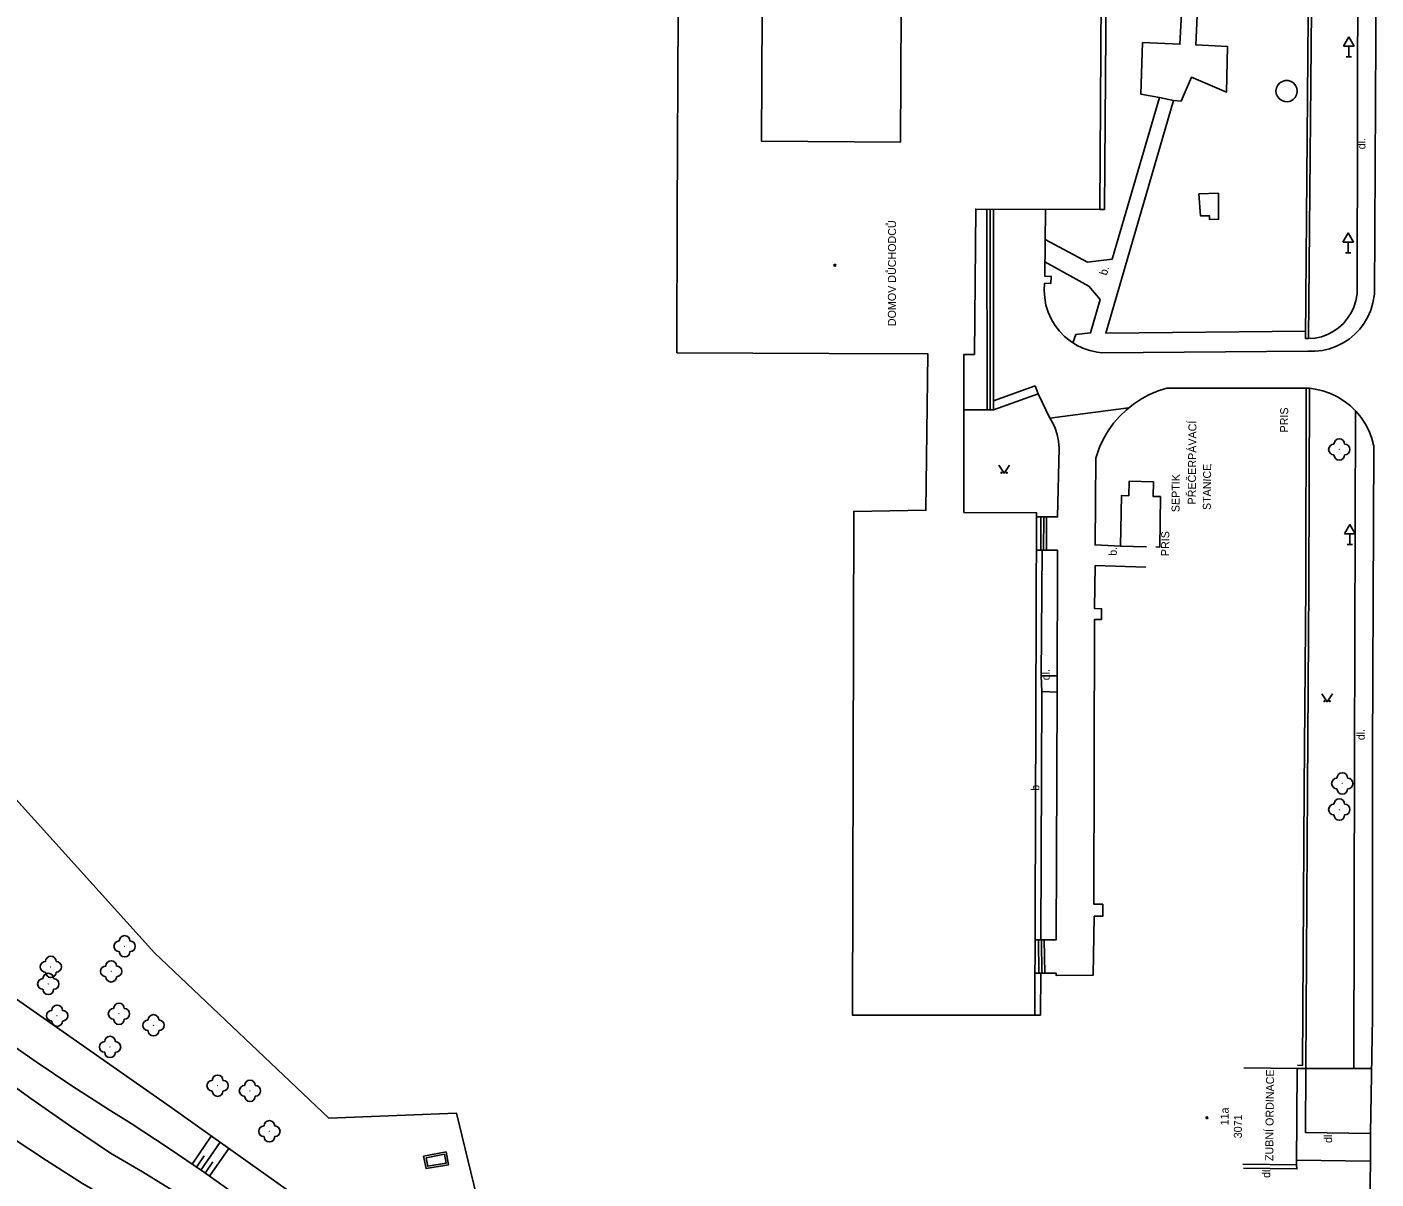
# Model space of a CAD drawing. Extents: x -584400 to -581602, y -1210894 to -1208793.
# Drawn here: x -582970.7 to -582844.2, y -1210177.5 to -1210069.5 of the extents above; entities that cross this region are included whole.
import ezdxf

# ---------------------------------------------------------------- set-up
doc = ezdxf.new("R2010")
doc.units = 0
for name, color, linetype in [('BUDOVY_MĚŘ', 7, 'Continuous'), ('BUDOVY_NEMĚŘ', 7, 'Continuous'), ('POMOC_POPIS', 7, 'Continuous'), ('ROZHRANÍ_PLOCH', 7, 'Continuous'), ('VÝŠKOPIS', 7, 'Continuous'), ('ZELEŇ', 7, 'Continuous'), ('ZN_BUDOV', 7, 'Continuous'), ('ZN_DOPLŇKOVÉ', 7, 'Continuous'), ('ZN_KULTUR', 7, 'Continuous'), ('Č_POPIS_EVID', 7, 'Continuous')]:
    doc.layers.add(name, color=color, linetype=linetype)

msp = doc.modelspace()

# ---------------------------------------------------------------- linework, layer by layer
at = {"layer": 'BUDOVY_MĚŘ'}
for points in [[(-582881.84, -1210100.23), (-582881.73, -1210086.6), (-582870.1, -1210086.64), (-582869.92, -1210061.85), (-582870.29, -1210061.85)], [(-582881.84, -1210100.23), (-582882.83, -1210100.23), (-582882.85, -1210115.05)], [(-582876.17, -1210162.16), (-582876.02, -1210115.06), (-582882.85, -1210115.05)], [(-582851.67, -1210176.18), (-582851.58, -1210167.14), (-582856.58, -1210167.09)], [(-582851.67, -1210176.18), (-582856.67, -1210176.12)]]:
    msp.add_lwpolyline(points, dxfattribs=at)
at = {"layer": 'BUDOVY_NEMĚŘ'}
msp.add_lwpolyline([(-582870.29, -1210061.85), (-582888.67, -1210061.71), (-582888.78, -1210080.34), (-582901.81, -1210080.23), (-582901.75, -1210068.26), (-582909.61, -1210068.22), (-582909.7, -1210087.02), (-582909.73, -1210100.07), (-582895.48, -1210100.14), (-582886.2, -1210100.18), (-582886.4, -1210114.82), (-582893.16, -1210114.94), (-582893.29, -1210162.14), (-582876.17, -1210162.16)], dxfattribs=at)
at = {"layer": 'ROZHRANÍ_PLOCH'}
for points in [[(-582864.49, -1210076.14), (-582866.25, -1210075.83), (-582866.08, -1210070.99), (-582862.58, -1210071.15), (-582862.05, -1210061.26)], [(-582860.63, -1210060.94), (-582861.09, -1210071.22), (-582858.13, -1210071.35), (-582858.21, -1210075.63), (-582861.51, -1210074.25), (-582862.47, -1210076.5), (-582863.17, -1210076.41)], [(-582869.92, -1210061.85), (-582869.47, -1210061.85), (-582869.65, -1210086.64), (-582870.1, -1210086.64)], [(-582845.91, -1210062.34), (-582845.98, -1210094.55)], [(-582875.28, -1210093.55), (-582875.31, -1210094.24), (-582875.26, -1210094.93), (-582875.14, -1210095.6), (-582874.93, -1210096.26), (-582874.65, -1210096.89), (-582874.3, -1210097.48), (-582873.88, -1210098.03), (-582873.4, -1210098.53), (-582872.87, -1210098.96), (-582872.29, -1210099.34), (-582871.67, -1210099.64), (-582871.02, -1210099.87), (-582870.35, -1210100.02), (-582869.89, -1210100.08), (-582850.6, -1210099.93), (-582849.91, -1210099.93), (-582849.23, -1210099.85), (-582848.56, -1210099.69), (-582847.91, -1210099.46), (-582847.29, -1210099.15), (-582846.72, -1210098.78), (-582846.19, -1210098.33), (-582845.72, -1210097.84), (-582845.31, -1210097.28), (-582844.96, -1210096.69), (-582844.69, -1210096.06), (-582844.49, -1210095.4), (-582844.35, -1210094.57), (-582844.2, -1210064.54)], [(-582851.58, -1210075.55), (-582851.62, -1210075.27), (-582851.74, -1210075.01), (-582851.92, -1210074.8), (-582852.16, -1210074.64), (-582852.43, -1210074.56), (-582852.71, -1210074.56), (-582852.98, -1210074.63), (-582853.22, -1210074.78), (-582853.41, -1210074.99), (-582853.53, -1210075.24), (-582853.58, -1210075.52), (-582853.55, -1210075.8), (-582853.44, -1210076.06), (-582853.26, -1210076.28), (-582853.03, -1210076.44), (-582852.76, -1210076.53), (-582852.48, -1210076.54), (-582852.21, -1210076.48), (-582851.96, -1210076.33), (-582851.77, -1210076.13), (-582851.64, -1210075.88), (-582851.58, -1210075.6), (-582851.58, -1210075.55)], [(-582875.21, -1210089.45), (-582871.26, -1210091.59), (-582868.94, -1210091.3), (-582864.49, -1210076.14)], [(-582863.17, -1210076.41), (-582869.54, -1210098.22), (-582850.82, -1210098.03)], [(-582864.49, -1210076.14), (-582863.17, -1210076.41)], [(-582860.81, -1210085.17), (-582858.98, -1210085.12), (-582858.96, -1210087.56), (-582859.82, -1210087.57), (-582859.82, -1210087.23), (-582860.64, -1210087.24), (-582860.81, -1210085.17)], [(-582880.67, -1210086.6), (-582880.66, -1210105.42)], [(-582880.36, -1210105.42), (-582880.37, -1210086.61)], [(-582880.07, -1210086.61), (-582880.06, -1210105.42)], [(-582875.18, -1210086.62), (-582875.25, -1210092.88), (-582874.64, -1210092.91), (-582874.67, -1210093.58)], [(-582872.63, -1210099.13), (-582872.34, -1210098.34), (-582870.96, -1210098.2), (-582870.06, -1210095.09), (-582871.12, -1210093.84), (-582875.24, -1210091.56)], [(-582875.28, -1210093.55), (-582874.67, -1210093.58)], [(-582850.52, -1210098.74), (-582849.92, -1210098.69), (-582849.32, -1210098.56), (-582848.75, -1210098.35), (-582848.21, -1210098.07), (-582847.71, -1210097.72), (-582847.26, -1210097.31), (-582846.86, -1210096.84), (-582846.54, -1210096.33), (-582846.28, -1210095.78), (-582846.09, -1210095.2), (-582845.98, -1210094.55)], [(-582880.06, -1210104.57), (-582876.14, -1210103.16)], [(-582880.06, -1210105.42), (-582875.87, -1210103.91)], [(-582875.87, -1210103.91), (-582876.14, -1210103.16)], [(-582875.87, -1210103.91), (-582874.77, -1210106.21)], [(-582850.44, -1210103.4), (-582863.8, -1210103.39), (-582864.63, -1210103.65), (-582865.43, -1210103.99), (-582866.2, -1210104.39), (-582866.92, -1210104.87), (-582867.6, -1210105.41), (-582868.23, -1210106.01), (-582868.8, -1210106.67), (-582869.3, -1210107.37), (-582869.74, -1210108.12), (-582870.11, -1210108.91), (-582870.47, -1210109.95), (-582870.54, -1210118.07), (-582868.14, -1210118.18)], [(-582844.73, -1210173.24), (-582844.54, -1210162.33), (-582844.52, -1210137.5), (-582844.4, -1210108.82), (-582844.58, -1210108.1), (-582844.85, -1210107.41), (-582845.19, -1210106.76), (-582845.6, -1210106.14), (-582846.07, -1210105.57), (-582846.6, -1210105.05), (-582847.18, -1210104.6), (-582847.81, -1210104.21), (-582848.48, -1210103.89), (-582849.18, -1210103.64), (-582849.9, -1210103.47), (-582850.44, -1210103.4)], [(-582880.66, -1210105.42), (-582882.84, -1210105.42)], [(-582880.36, -1210105.42), (-582880.66, -1210105.42)], [(-582880.06, -1210105.42), (-582880.36, -1210105.42)], [(-582874.77, -1210106.21), (-582867.39, -1210105.23)], [(-582846.12, -1210105.52), (-582846.23, -1210137.75), (-582846.28, -1210167.16)], [(-582875.08, -1210115.45), (-582874.05, -1210115.45), (-582873.91, -1210109), (-582873.96, -1210108.36), (-582874.08, -1210107.74), (-582874.28, -1210107.13), (-582874.56, -1210106.55), (-582874.77, -1210106.21)], [(-582864.85, -1210118.27), (-582864.48, -1210118.28), (-582864.41, -1210113.55), (-582865.1, -1210113.53), (-582865.06, -1210112.16), (-582867.34, -1210112.1), (-582867.38, -1210113.47), (-582868.07, -1210113.45), (-582868.14, -1210118.18), (-582865.72, -1210118.25)], [(-582876.02, -1210115.44), (-582875.62, -1210115.45)], [(-582875.63, -1210118.57), (-582875.62, -1210115.45)], [(-582875.62, -1210115.45), (-582875.35, -1210115.45)], [(-582875.35, -1210115.45), (-582875.08, -1210115.45), (-582875.09, -1210118.57), (-582875.36, -1210118.57)], [(-582875.35, -1210115.45), (-582875.36, -1210118.57)], [(-582875.63, -1210118.57), (-582876.03, -1210118.57)], [(-582875.5, -1210118.57), (-582875.63, -1210118.57)], [(-582875.5, -1210118.57), (-582875.58, -1210130.34)], [(-582875.36, -1210118.57), (-582875.5, -1210118.57)], [(-582874.08, -1210131.87), (-582874.05, -1210118.57), (-582875.09, -1210118.57)], [(-582870.53, -1210120.02), (-582870.58, -1210124.05), (-582869.93, -1210124.06), (-582869.93, -1210125.05), (-582870.58, -1210125.05), (-582870.65, -1210151.76), (-582869.82, -1210151.76)], [(-582870.53, -1210120.02), (-582865.78, -1210120.15)], [(-582875.58, -1210130.34), (-582874.08, -1210130.34)], [(-582875.58, -1210130.34), (-582875.54, -1210131.82)], [(-582875.54, -1210131.82), (-582875.62, -1210155.08)], [(-582874.08, -1210131.87), (-582875.54, -1210131.82)], [(-582875.3, -1210155.08), (-582874.17, -1210155.08), (-582874.08, -1210131.87)], [(-582870.63, -1210152.86), (-582869.8, -1210152.86), (-582869.82, -1210151.76)], [(-582870.63, -1210152.86), (-582870.73, -1210158.4), (-582874.18, -1210158.44), (-582874.18, -1210158.2)], [(-582962.83, -1210175.09), (-582966.59, -1210172.56), (-582970.31, -1210169.96), (-582973.99, -1210167.29), (-582977.61, -1210164.56), (-582981.19, -1210161.77), (-582984.72, -1210158.92), (-582988.19, -1210156), (-582990.55, -1210153.96)], [(-582876.15, -1210155.08), (-582875.84, -1210155.08)], [(-582875.84, -1210155.08), (-582875.8, -1210158.2)], [(-582875.84, -1210155.08), (-582875.62, -1210155.08)], [(-582875.62, -1210155.08), (-582875.57, -1210155.08)], [(-582875.57, -1210155.08), (-582875.53, -1210158.2)], [(-582875.57, -1210155.08), (-582875.3, -1210155.08), (-582875.26, -1210158.2), (-582875.53, -1210158.2)], [(-582875.8, -1210158.2), (-582876.16, -1210158.2)], [(-582875.63, -1210158.2), (-582875.8, -1210158.2)], [(-582875.63, -1210158.2), (-582875.64, -1210162.16)], [(-582875.53, -1210158.2), (-582875.63, -1210158.2)], [(-582875.26, -1210158.2), (-582874.18, -1210158.2)], [(-582876.17, -1210162.16), (-582875.64, -1210162.16)], [(-582973.11, -1210164.21), (-582969.81, -1210166.52), (-582966.46, -1210168.78), (-582963.06, -1210170.96), (-582960.89, -1210172.31), (-582957.44, -1210174.57), (-582954.03, -1210176.9), (-582950.66, -1210179.3), (-582947.35, -1210181.76), (-582944.08, -1210184.29), (-582940.86, -1210186.88), (-582937.69, -1210189.53), (-582934.57, -1210192.24), (-582931.51, -1210195.01), (-582929.31, -1210197.07), (-582927.03, -1210199.69), (-582924.81, -1210202.37), (-582922.65, -1210205.1), (-582920.55, -1210207.88), (-582918.52, -1210210.71), (-582916.56, -1210213.58), (-582914.66, -1210216.5), (-582912.83, -1210219.46), (-582911.09, -1210222.41)], [(-582850.79, -1210167.16), (-582850.81, -1210173.15), (-582844.73, -1210173.24)], [(-582850.79, -1210167.16), (-582846.28, -1210167.16)], [(-582846.28, -1210167.16), (-582844.62, -1210167.16)], [(-582844.84, -1210202.24), (-582844.73, -1210173.24)], [(-582962.83, -1210175.09), (-582959.84, -1210176.83), (-582956.89, -1210178.64), (-582953.99, -1210180.51), (-582951.13, -1210182.45), (-582948.31, -1210184.46), (-582945.55, -1210186.54), (-582942.83, -1210188.67), (-582940.16, -1210190.87), (-582937.54, -1210193.13), (-582934.98, -1210195.45), (-582931.39, -1210198.89)], [(-582931.36, -1210174.95), (-582931.15, -1210176.19), (-582933.25, -1210176.53), (-582933.48, -1210175.36)], [(-582931.36, -1210174.95), (-582933.48, -1210175.36)], [(-582931.52, -1210175.19), (-582931.38, -1210176.02), (-582933.09, -1210176.31), (-582933.24, -1210175.52)], [(-582931.52, -1210175.19), (-582933.24, -1210175.52)], [(-582851.67, -1210176.18), (-582851.62, -1210176.55), (-582856.62, -1210176.5)], [(-582844.74, -1210175.84), (-582851.67, -1210175.75)]]:
    msp.add_lwpolyline(points, dxfattribs=at)
at = {"layer": 'VÝŠKOPIS'}
for points in [[(-582971.64, -1210160.64), (-582957.28, -1210170.72), (-582938.82, -1210183.84)], [(-582934.33, -1210201.85), (-582936.75, -1210199.45), (-582939.23, -1210197.12), (-582941.76, -1210194.84), (-582944.35, -1210192.62), (-582946.99, -1210190.46), (-582949.68, -1210188.37), (-582952.41, -1210186.34), (-582955.19, -1210184.37), (-582958.02, -1210182.47), (-582960.9, -1210180.64), (-582963.81, -1210178.88), (-582965.46, -1210177.92), (-582968.83, -1210175.78), (-582972.16, -1210173.57)], [(-582953.39, -1210173.48), (-582955.19, -1210176.1)], [(-582952.57, -1210174.05), (-582954.37, -1210176.66)], [(-582951.75, -1210174.63), (-582953.55, -1210177.24)], [(-582954.05, -1210175.32), (-582954.78, -1210176.38)], [(-582953.23, -1210175.89), (-582953.96, -1210176.95)]]:
    msp.add_lwpolyline(points, dxfattribs=at)
at = {"layer": 'ZELEŇ'}
for centre in [(-582847.64, -1210109.13), (-582847.36, -1210140.43), (-582847.64, -1210142.88), (-582961.51, -1210155.69), (-582968.43, -1210157.62), (-582962.77, -1210158.04), (-582968.67, -1210159.22), (-582967.84, -1210162.2), (-582962.04, -1210162.02), (-582958.81, -1210163.1), (-582962.88, -1210165.13), (-582952.79, -1210168.76), (-582949.76, -1210169.24), (-582947.94, -1210173.03)]:
    msp.add_circle(centre, 0.0005, dxfattribs=at)
for centre, start, end in [((-582847.64, -1210108.63), 0, 180), ((-582848.14, -1210109.13), 90, 270), ((-582847.14, -1210109.13), 270, 90), ((-582847.64, -1210109.63), 180, 360), ((-582847.36, -1210139.93), 0, 180), ((-582847.86, -1210140.43), 90, 270), ((-582847.36, -1210140.93), 180, 360), ((-582846.86, -1210140.43), 270, 90), ((-582847.64, -1210142.38), 0, 180), ((-582848.14, -1210142.88), 90, 270), ((-582847.64, -1210143.38), 180, 360), ((-582847.14, -1210142.88), 270, 90), ((-582961.51, -1210155.19), 0, 180), ((-582962.01, -1210155.69), 90, 270), ((-582961.51, -1210156.19), 180, 360), ((-582961.01, -1210155.69), 270, 90), ((-582968.93, -1210157.62), 90, 270), ((-582968.43, -1210157.12), 0, 180), ((-582967.93, -1210157.62), 270, 90), ((-582962.77, -1210157.54), 0, 180), ((-582969.17, -1210159.22), 90, 270), ((-582968.67, -1210158.72), 0, 180), ((-582968.43, -1210158.12), 180, 360), ((-582968.17, -1210159.22), 270, 90), ((-582963.27, -1210158.04), 90, 270), ((-582962.77, -1210158.54), 180, 360), ((-582962.27, -1210158.04), 270, 90), ((-582968.67, -1210159.72), 180, 360), ((-582967.84, -1210161.7), 0, 180), ((-582962.04, -1210161.52), 0, 180), ((-582968.34, -1210162.2), 90, 270), ((-582967.34, -1210162.2), 270, 90), ((-582962.54, -1210162.02), 90, 270), ((-582962.04, -1210162.52), 180, 360), ((-582961.54, -1210162.02), 270, 90), ((-582958.81, -1210162.6), 0, 180), ((-582967.84, -1210162.7), 180, 360), ((-582959.31, -1210163.1), 90, 270), ((-582958.81, -1210163.6), 180, 360), ((-582958.31, -1210163.1), 270, 90), ((-582963.38, -1210165.13), 90, 270), ((-582962.88, -1210164.63), 0, 180), ((-582962.38, -1210165.13), 270, 90), ((-582962.88, -1210165.63), 180, 360), ((-582953.29, -1210168.76), 90, 270), ((-582952.79, -1210168.26), 0, 180), ((-582952.29, -1210168.76), 270, 90), ((-582950.26, -1210169.24), 90, 270), ((-582949.76, -1210168.74), 0, 180), ((-582949.26, -1210169.24), 270, 90), ((-582952.79, -1210169.26), 180, 360), ((-582949.76, -1210169.74), 180, 360), ((-582948.44, -1210173.03), 90, 270), ((-582947.94, -1210172.53), 0, 180), ((-582947.44, -1210173.03), 270, 90), ((-582947.94, -1210173.53), 180, 360)]:
    msp.add_arc(centre, 0.5, start, end, dxfattribs=at)
at = {"layer": 'ZN_BUDOV'}
for centre in [(-582894.93, -1210091.87), (-582860.05, -1210171.76)]:
    msp.add_circle(centre, 0.0875, dxfattribs=at)
at = {"layer": 'ZN_DOPLŇKOVÉ'}
for p, q in [((-582846.76, -1210070.46), (-582847.26, -1210071.33)), ((-582847.26, -1210071.33), (-582846.26, -1210071.33)), ((-582846.76, -1210070.46), (-582846.26, -1210071.33)), ((-582846.76, -1210072.33), (-582846.76, -1210071.33)), ((-582847.01, -1210072.33), (-582846.51, -1210072.33)), ((-582846.8, -1210088.82), (-582847.3, -1210089.69)), ((-582846.8, -1210088.82), (-582846.3, -1210089.69)), ((-582847.3, -1210089.69), (-582846.3, -1210089.69)), ((-582846.8, -1210090.69), (-582846.8, -1210089.69)), ((-582847.05, -1210090.69), (-582846.55, -1210090.69)), ((-582846.65, -1210116.17), (-582847.15, -1210117.04)), ((-582846.65, -1210116.17), (-582846.15, -1210117.04)), ((-582847.15, -1210117.04), (-582846.15, -1210117.04)), ((-582846.9, -1210118.04), (-582846.4, -1210118.04)), ((-582846.65, -1210118.04), (-582846.65, -1210117.04))]:
    msp.add_line(p, q, dxfattribs=at)
for points in [[(-583056.57, -1210054.07), (-583048.98, -1210061.82), (-583041.52, -1210069.5), (-583020.8, -1210090.92), (-583001.61, -1210110.68), (-582976.04, -1210137.13), (-582958.7, -1210156.31), (-582942.37, -1210171.79), (-582930.4, -1210171.32), (-582927.16, -1210184.69), (-582908.32, -1210182.1)], [(-582850.82, -1210098.73), (-582850.49, -1210061.02)], [(-582850.19, -1210061.02), (-582850.52, -1210098.74)], [(-582850.82, -1210098.73), (-582850.52, -1210098.74)], [(-582850.44, -1210103.4), (-582850.49, -1210121.94), (-582850.63, -1210140.91), (-582850.79, -1210167.16), (-582851.58, -1210167.14)], [(-582851.57, -1210166.84), (-582851.08, -1210166.85), (-582850.93, -1210140.91), (-582850.79, -1210121.94), (-582850.75, -1210103.4)]]:
    msp.add_lwpolyline(points, dxfattribs=at)
at = {"layer": 'ZN_KULTUR'}
for points in [[(-582879.57, -1210110.61), (-582879.07, -1210111.36), (-582878.57, -1210110.61)], [(-582849.29, -1210132.03), (-582848.79, -1210132.78), (-582848.29, -1210132.03)]]:
    msp.add_lwpolyline(points, dxfattribs=at)
for centre in [(-582879.32, -1210111.31), (-582878.82, -1210111.31), (-582849.04, -1210132.73), (-582848.54, -1210132.73)]:
    msp.add_circle(centre, 0.05, dxfattribs=at)

# ---------------------------------------------------------------- texts
at = {"layer": 'POMOC_POPIS'}
for s, rotation, p in [('dl.', 89.8972, (-582845.19, -1210081)), ('DOMOV DŮCHODCŮ', 89.91, (-582889.21, -1210097.57)), ('b.', 73.7186, (-582869.44, -1210092.87)), ('PRIS', 89.5376, (-582852.45, -1210107.54)), ('PŘEČERPÁVACÍ', 89.5061, (-582861.1, -1210114.29)), ('STANICE', 89.5061, (-582859.69, -1210114.81)), ('SEPTIK', 89.5061, (-582862.62, -1210115.01)), ('PRIS', 89.5061, (-582863.6, -1210119.13)), ('b.', 89.5061, (-582868.5, -1210119.1)), ('dl.', 89.8875, (-582874.79, -1210130.76)), ('dl.', 89.8875, (-582845.26, -1210136.38)), ('b', 89.8875, (-582875.77, -1210141.12)), ('ZUBNÍ ORDINACE', 89.4168, (-582853.84, -1210175.82)), ('dl.', 89.4168, (-582848.32, -1210174.13)), ('dl.', 89.4168, (-582854.12, -1210177.4))]:
    msp.add_text(s, height=0.75, rotation=rotation, dxfattribs=at).set_placement(p)
at = {"layer": 'Č_POPIS_EVID'}
for s, p in [('11a', (-582858.03, -1210172.48)), ('3071', (-582856.78, -1210173.69))]:
    msp.add_text(s, height=0.75, rotation=89.4296, dxfattribs=at).set_placement(p)

doc.saveas('drawing.dxf')
